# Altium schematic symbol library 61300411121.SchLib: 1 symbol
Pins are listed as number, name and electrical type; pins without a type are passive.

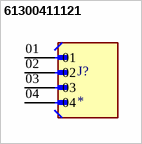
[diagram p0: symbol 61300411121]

## 61300411121
designator J?
<a href="https://pricing.snapeda.com/parts/61300411121/W%C3%BCrth%20Elektronik/view-part?ref=eda">Check availability</a>; MF: {'manufacturer': u'Wurth Electronics'}
footprint WURTH_61300411121
pins: 01, 02, 03, 04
